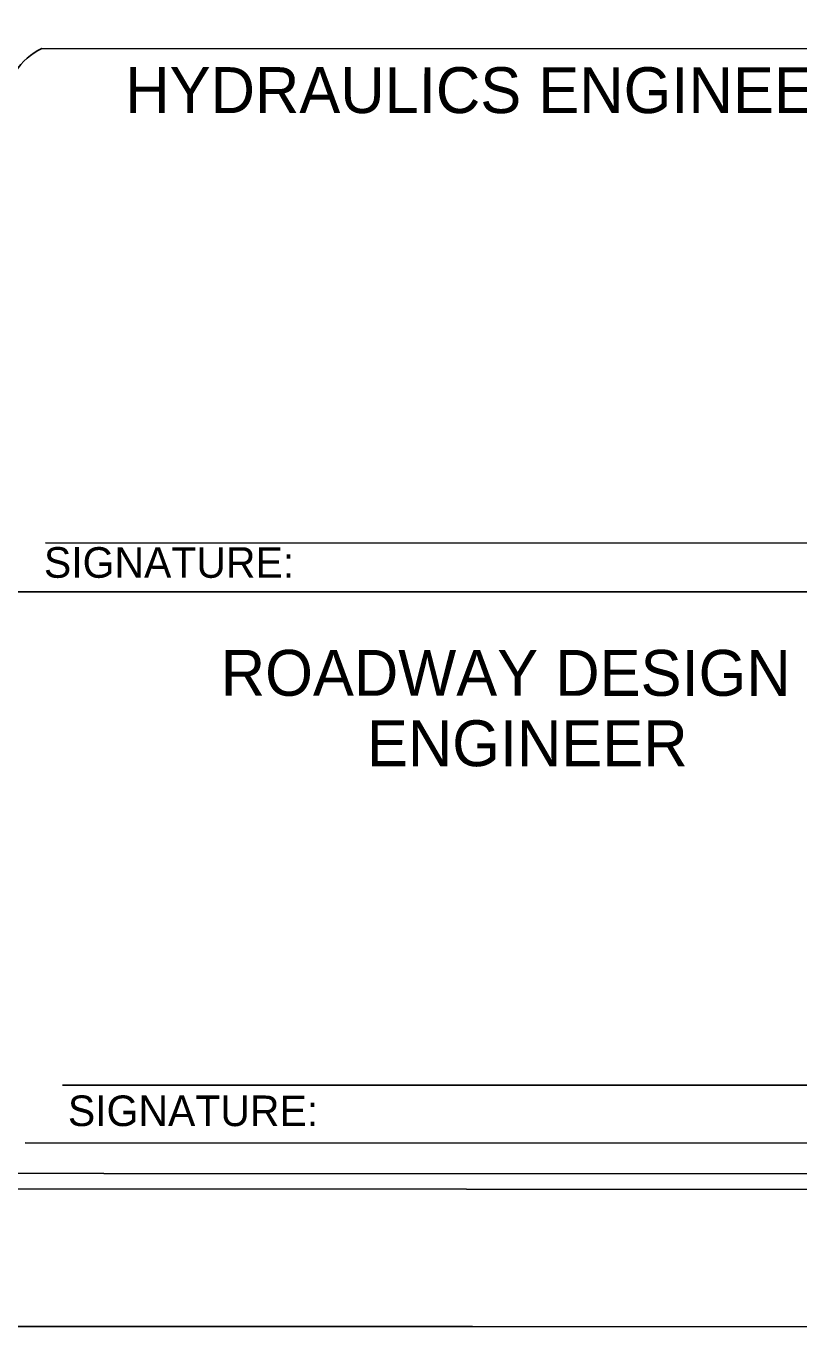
# Model space of a CAD drawing. Extents: x 2110629 to 2114002, y 669321 to 671542.
# Drawn here: x 2112822.3 to 2113039.5, y 669648.2 to 670014 of the extents above; entities that cross this region are included whole.
import ezdxf

# ---------------------------------------------------------------- set-up
doc = ezdxf.new("R2010")
doc.units = 0
for name, color, linetype in [('Exist Roads Curbs', 7, 'Continuous'), ('Exist Roads EOP Other Text', 7, 'Continuous'), ('Exist Structure Minor Catch Basin', 7, 'Continuous'), ('Exist Utilities Water Test Hole SUE LOS A Text', 7, 'Continuous')]:
    doc.layers.add(name, color=color, linetype=linetype)

msp = doc.modelspace()

# ---------------------------------------------------------------- linework, layer by layer
at = {"layer": 'Exist Roads Curbs'}
msp.add_line((2110628.92, 669648.68), (2113527.5, 669648.19), dxfattribs=at)
at = {"layer": 'Exist Roads EOP Other Text'}
msp.add_lwpolyline([(2110651.3, 669687.3), (2113519.77, 669686.81), (2113520.07, 671502.9), (2110651.61, 671503.39)], close=True, dxfattribs=at)
at = {"layer": 'Exist Structure Minor Catch Basin'}
for p, q in [((2112826.8, 670007.62), (2113179.19, 670007.56)), ((2112827.84, 669868.64), (2113076.13, 669868.6)), ((2112816.51, 669854.9), (2113188.06, 669854.84)), ((2112832.56, 669716.21), (2113076.12, 669716.15))]:
    msp.add_line(p, q, dxfattribs=at)
for points in [[(2112822.13, 669699.95), (2113170.83, 669699.89)], [(2110933.59, 669691.64), (2113481.04, 669691.21)]]:
    msp.add_lwpolyline(points, dxfattribs=at)
msp.add_arc((2112834.1, 669991.8), 17.43, 114.7561, 179.9376, dxfattribs=at)
at = {"layer": 'Exist Utilities Water Test Hole SUE LOS A Text'}
msp.add_lwpolyline([(2113527.82, 671541.54), (2110629.24, 671542.03), (2110628.92, 669648.68), (2113527.5, 669648.19)], close=True, dxfattribs=at)

# ---------------------------------------------------------------- texts
at = {"layer": 'Exist Structure Minor Catch Basin'}
for s, height, p in [(' HYDRAULICS ENGINEER', 12.9094, (2112845.43, 669989.52)), ('SIGNATURE:', 8.605, (2112827.37, 669858.85)), ('ROADWAY DESIGN', 12.9083, (2112877.07, 669825.67)), ('ENGINEER', 12.908, (2112918.12, 669805.87)), ('SIGNATURE:', 8.605, (2112834.11, 669704.68))]:
    msp.add_text(s, height=height, rotation=359.9903, dxfattribs=at).set_placement(p)

doc.saveas('drawing.dxf')
